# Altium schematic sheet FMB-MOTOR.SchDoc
size A4
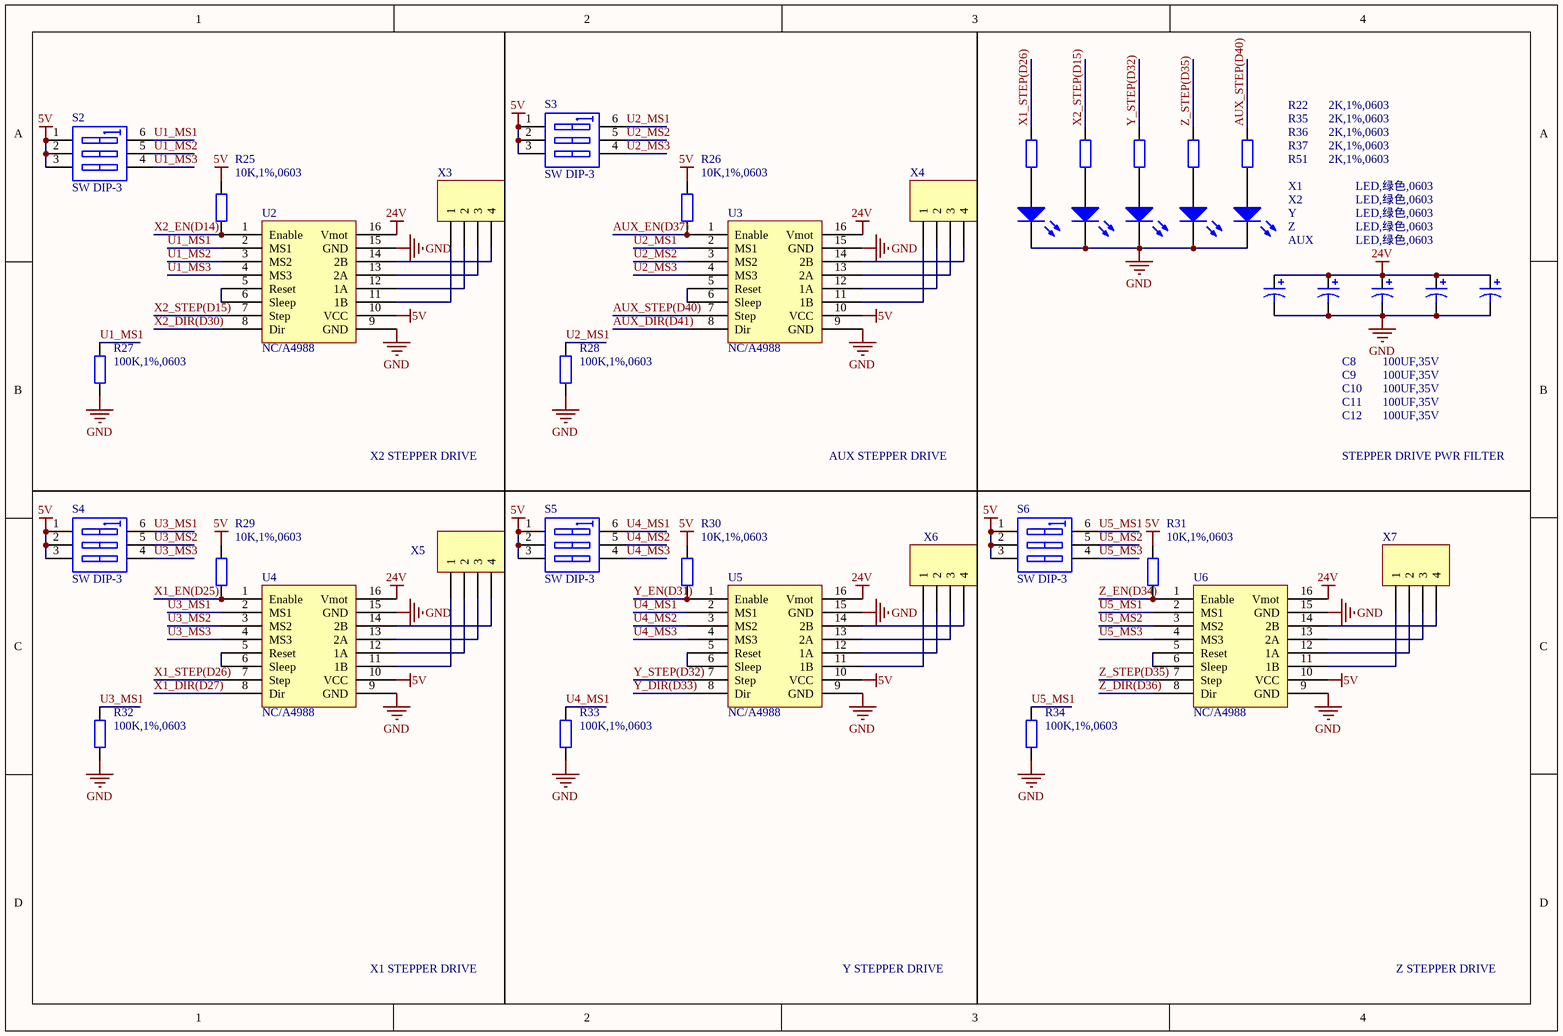
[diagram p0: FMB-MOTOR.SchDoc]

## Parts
AUX  LED,绿色,0603  [LED-0603]
C8  100UF,35V  [EC-5X5.3]
C9  100UF,35V  [EC-5X5.3]
C10  100UF,35V  [EC-5X5.3]
C11  100UF,35V  [EC-5X5.3]
C12  100UF,35V  [EC-5X5.3]
R22  2K,1%,0603  [RC0603]
R25  10K,1%,0603  [RC0603]
R26  10K,1%,0603  [RC0603]
R27  100K,1%,0603  [RC0603]
R28  100K,1%,0603  [RC0603]
R29  10K,1%,0603  [RC0603]
R30  10K,1%,0603  [RC0603]
R31  10K,1%,0603  [RC0603]
R32  100K,1%,0603  [RC0603]
R33  100K,1%,0603  [RC0603]
R34  100K,1%,0603  [RC0603]
R35  2K,1%,0603  [RC0603]
R36  2K,1%,0603  [RC0603]
R37  2K,1%,0603  [RC0603]
R51  2K,1%,0603  [RC0603]
S2  SW DIP-3  [DIP-3-SW]
S3  SW DIP-3  [DIP-3-SW]
S4  SW DIP-3  [DIP-3-SW]
S5  SW DIP-3  [DIP-3-SW]
S6  SW DIP-3  [DIP-3-SW]
U2  NC/A4988  [A4988]
U3  NC/A4988  [A4988]
U4  NC/A4988  [A4988]
U5  NC/A4988  [A4988]
U6  NC/A4988  [A4988]
X1  LED,绿色,0603  [LED-0603]
X2  LED,绿色,0603  [LED-0603]
X3  Molex 70543-0038  [DIP-1*4-2.54]  (value not drawn)
X4  Molex 70543-0038  [DIP-1*4-2.54]  (value not drawn)
X5  Molex 70543-0038  [DIP-1*4-2.54]  (value not drawn)
X6  Molex 70543-0038  [DIP-1*4-2.54]  (value not drawn)
X7  Molex 70543-0038  [DIP-1*4-2.54]  (value not drawn)
Y  LED,绿色,0603  [LED-0603]
Z  LED,绿色,0603  [LED-0603]

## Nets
5V: R25.1 R26.1 R29.1 R30.1 R31.1 S2.1(A1) S2.2(A2) S2.3(A3) S3.1(A1) S3.2(A2) S3.3(A3) S4.1(A1) S4.2(A2) S4.3(A3) S5.1(A1) S5.2(A2) S5.3(A3) S6.1(A1) S6.2(A2) S6.3(A3) U2.10(VCC) U3.10(VCC) U4.10(VCC) U5.10(VCC) U6.10(VCC)
24V: C8.1 C9.1 C10.1 C11.1 C12.1 U2.16(Vmot) U3.16(Vmot) U4.16(Vmot) U5.16(Vmot) U6.16(Vmot)
GND: AUX.2(K) C8.2 C9.2 C10.2 C11.2 C12.2 R27.2 R28.2 R32.2 R33.2 R34.2 U2.9(GND) U2.15(GND) U3.9(GND) U3.15(GND) U4.9(GND) U4.15(GND) U5.9(GND) U5.15(GND) U6.9(GND) U6.15(GND) X1.2(K) X2.2(K) Y.2(K) Z.2(K)
AUX_DIR(D41): U3.8(Dir)
AUX_EN(D37): R26.2 U3.1(Enable)
AUX_STEP(D40): R51.1 U3.7(Step)
U1_MS1: R27.1 S2.6(B1) U2.2(MS1)
U1_MS2: S2.5(B2) U2.3(MS2)
U1_MS3: S2.4(B3) U2.4(MS3)
U2_MS1: R28.1 S3.6(B1) U3.2(MS1)
U2_MS2: S3.5(B2) U3.3(MS2)
U2_MS3: S3.4(B3) U3.4(MS3)
U3_MS1: R32.1 S4.6(B1) U4.2(MS1)
U3_MS2: S4.5(B2) U4.3(MS2)
U3_MS3: S4.4(B3) U4.4(MS3)
U4_MS1: R33.1 S5.6(B1) U5.2(MS1)
U4_MS2: S5.5(B2) U5.3(MS2)
U4_MS3: S5.4(B3) U5.4(MS3)
U5_MS1: R34.1 S6.6(B1) U6.2(MS1)
U5_MS2: S6.5(B2) U6.3(MS2)
U5_MS3: S6.4(B3) U6.4(MS3)
X1_DIR(D27): U4.8(Dir)
X1_EN(D25): R29.2 U4.1(Enable)
X1_STEP(D26): R22.1 U4.7(Step)
X2_DIR(D30): U2.8(Dir)
X2_EN(D14): R25.2 U2.1(Enable)
X2_STEP(D15): R35.1 U2.7(Step)
Y_DIR(D33): U5.8(Dir)
Y_EN(D31): R30.2 U5.1(Enable)
Y_STEP(D32): R36.1 U5.7(Step)
Z_DIR(D36): U6.8(Dir)
Z_EN(D34): R31.2 U6.1(Enable)
Z_STEP(D35): R37.1 U6.7(Step)
NetAUX_1: AUX.1(A) R51.2
NetR22_2: R22.2 X1.1(A)
NetR35_2: R35.2 X2.1(A)
NetR36_2: R36.2 Y.1(A)
NetR37_2: R37.2 Z.1(A)
NetU2_5: U2.5(Reset) U2.6(Sleep)
NetU2_11: U2.11(1B) X3.1
NetU2_12: U2.12(1A) X3.2
NetU2_13: U2.13(2A) X3.3
NetU2_14: U2.14(2B) X3.4
NetU3_5: U3.5(Reset) U3.6(Sleep)
NetU3_11: U3.11(1B) X4.1
NetU3_12: U3.12(1A) X4.2
NetU3_13: U3.13(2A) X4.3
NetU3_14: U3.14(2B) X4.4
NetU4_5: U4.5(Reset) U4.6(Sleep)
NetU4_11: U4.11(1B) X5.1
NetU4_12: U4.12(1A) X5.2
NetU4_13: U4.13(2A) X5.3
NetU4_14: U4.14(2B) X5.4
NetU5_5: U5.5(Reset) U5.6(Sleep)
NetU5_11: U5.11(1B) X6.1
NetU5_12: U5.12(1A) X6.2
NetU5_13: U5.13(2A) X6.3
NetU5_14: U5.14(2B) X6.4
NetU6_5: U6.5(Reset) U6.6(Sleep)
NetU6_11: U6.11(1B) X7.1
NetU6_12: U6.12(1A) X7.2
NetU6_13: U6.13(2A) X7.3
NetU6_14: U6.14(2B) X7.4

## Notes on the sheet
- X2 STEPPER DRIVE
- AUX STEPPER DRIVE
- STEPPER DRIVE PWR FILTER
- X1 STEPPER DRIVE
- Y STEPPER DRIVE
- Z STEPPER DRIVE

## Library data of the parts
AUX X1 X2 Y Z = LED0: Typical INFRARED GaAs LED
C8-C12 = Cap Pol3: Polarized Capacitor (Surface Mount); Value: 100pF
R22 R25-R37 R51 = Res2: Resistor; Value: 1K
S2-S6 = SW DIP-3: DIP Switch, 3 Position, SPST
U2-U6 = A4988
X3-X7 = Header 4: Header, 4-Pin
